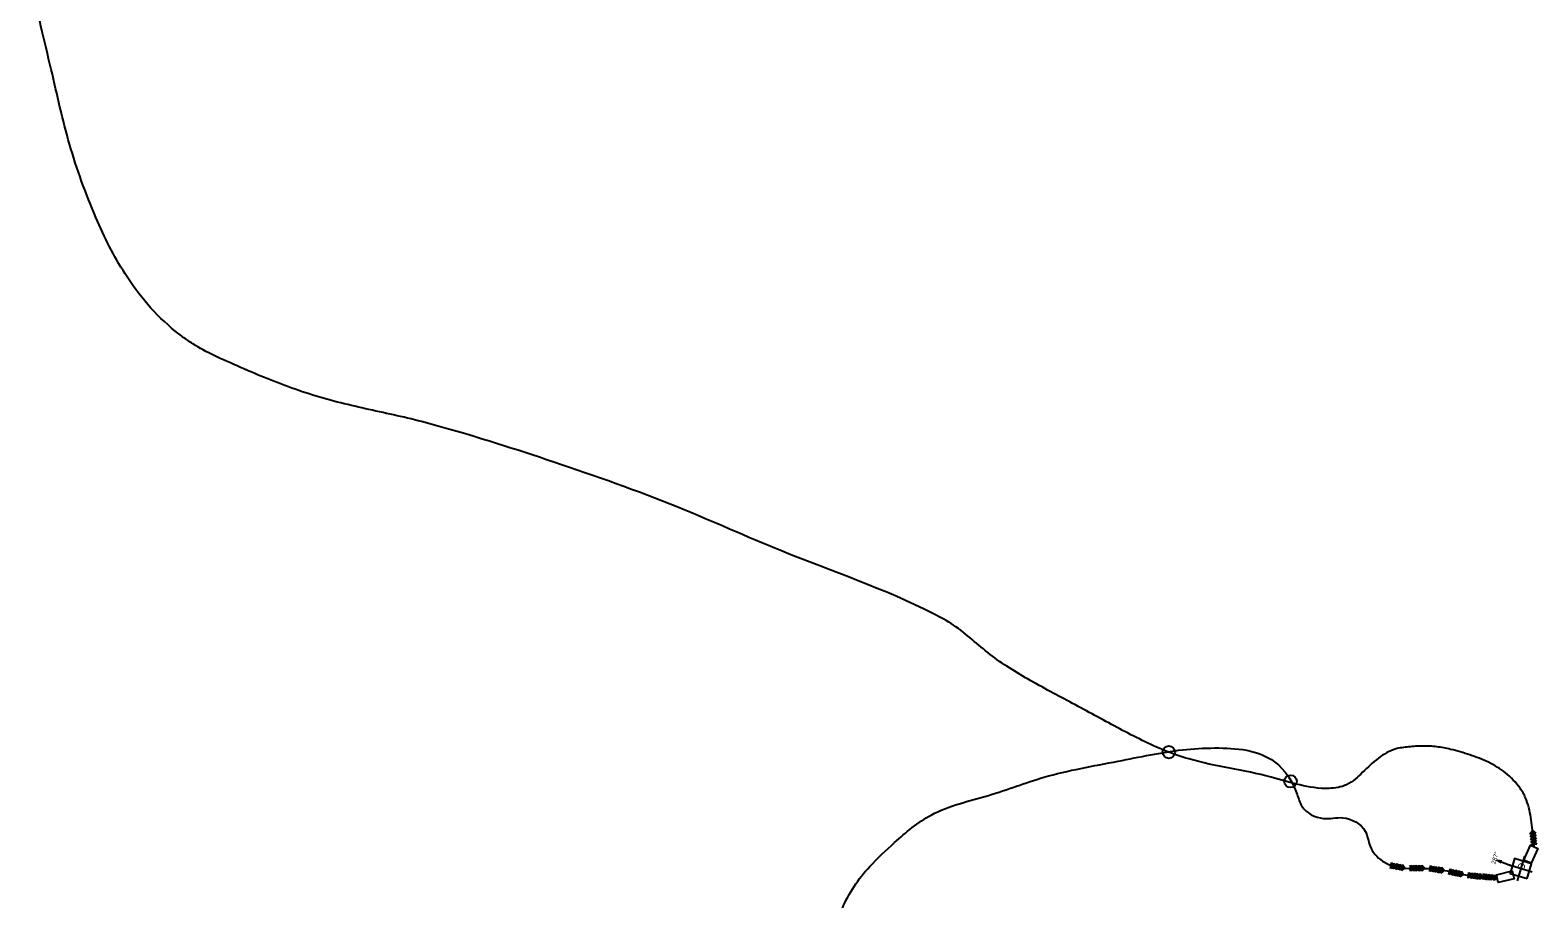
# Model space of a CAD drawing. Extents: x 387828 to 391861, y 7650362 to 7652502.
# Drawn here: x 387882.1 to 388052.5, y 7652108.1 to 7652206.3 of the extents above; entities that cross this region are included whole.
import ezdxf

# ---------------------------------------------------------------- set-up
doc = ezdxf.new("R2010")
doc.units = 0
for name, color, linetype in [('Blocos de area de avaliacao', 7, 'Continuous'), ('Blocos de producao br', 7, 'Continuous'), ('Cruzamento', 7, 'Continuous'), ('Dutos flexiveis', 7, 'Continuous'), ('Sinalizacao', 7, 'Continuous'), ('Texto dos gasodutos', 7, 'Continuous')]:
    doc.layers.add(name, color=color, linetype=linetype)

msp = doc.modelspace()

# ---------------------------------------------------------------- linework, layer by layer
at = {"layer": 'Blocos de area de avaliacao'}
for p, q in [((388047.9603292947, 7652112.509162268), (388049.6660734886, 7652111.858066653)), ((388051.901559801, 7652111.174610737), (388049.34319681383, 7652111.956779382)), ((388051.04635578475, 7652112.952465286), (388050.1984008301, 7652110.1789248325))]:
    msp.add_line(p, q, dxfattribs=at)
msp.add_lwpolyline([(388048.38287911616, 7652112.214074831), (388047.9603292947, 7652112.509162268), (388048.4720322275, 7652112.447638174)], dxfattribs=at)
at = {"layer": 'Blocos de producao br'}
for points in [[(388050.96772789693, 7652112.53604999), (388051.70532456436, 7652114.2162810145), (388052.54315073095, 7652113.848487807), (388051.8055540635, 7652112.168256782)], [(388047.8539045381, 7652110.870332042), (388049.6345597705, 7652111.313606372), (388049.85559312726, 7652110.425704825), (388048.0749378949, 7652109.982430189)]]:
    msp.add_lwpolyline(points, close=True, dxfattribs=at)
at = {"layer": 'Cruzamento'}
for centre in [(388010.8431242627, 7652124.717128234), (388024.58300245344, 7652121.434327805)]:
    msp.add_circle(centre, 0.7050177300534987, dxfattribs=at)
at = {"layer": 'Dutos flexiveis'}
for points in [[(388052.1426093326, 7652114.027375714), (388051.91000000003, 7652116.22), (388051.516732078, 7652118.479517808), (388051.14450636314, 7652119.574611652), (388050.87385052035, 7652120.114166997), (388050.5313486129, 7652120.648651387), (388048.8822293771, 7652122.386417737), (388046.96220465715, 7652123.585584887), (388044.864725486, 7652124.414286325), (388042.6832428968, 7652125.040655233), (388041.12194433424, 7652125.332635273), (388039.5223364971, 7652125.41788934), (388037.9409747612, 7652125.321987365), (388036.4344148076, 7652125.070498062), (388034.5261635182, 7652124.059678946), (388032.74273232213, 7652122.451738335), (388030.93271248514, 7652121.0424277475), (388028.944694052, 7652120.627499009), (388022.38694814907, 7652121.9071770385), (388013.09184148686, 7652123.964030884), (388010.41227454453, 7652124.8882036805), (388007.83105075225, 7652126.058778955), (388002.7895391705, 7652128.704348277), (387997.75690481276, 7652131.4113791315), (387992.81115970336, 7652134.249455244), (387990.64983336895, 7652135.767823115), (387988.5990002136, 7652137.464796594), (387986.50889736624, 7652139.085880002), (387984.22976226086, 7652140.376578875), (387967.04578478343, 7652147.475676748), (387955.33999511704, 7652152.4103787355), (387941.3134736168, 7652157.51206), (387928.35414746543, 7652161.552506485), (387925.2033695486, 7652162.382226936), (387922.02416302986, 7652163.103111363), (387918.84024231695, 7652163.814135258), (387915.67532242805, 7652164.614274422), (387909.3855311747, 7652166.7620087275), (387906.3099526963, 7652168.043193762), (387903.25013183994, 7652169.41), (387900.8121295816, 7652170.705623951), (387899.6609988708, 7652171.468749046), (387898.5465346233, 7652172.320802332), (387895.4376369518, 7652175.326235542), (387892.8787127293, 7652178.785263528), (387891.08650654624, 7652181.900448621), (387889.5796160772, 7652185.140767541), (387886.60210852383, 7652193.429089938), (387884.526090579, 7652201.868390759), (387882.3878279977, 7652211.720953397), (387882.16443922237, 7652213.858641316), (387882.2749983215, 7652216.02211005), (387882.64460036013, 7652218.190555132), (387883.19834009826, 7652220.343171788), (387883.7089428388, 7652221.81122959), (387884.35989165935, 7652223.188933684), (387885.15630787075, 7652224.503875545), (387886.1033140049, 7652225.783645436), (387888.4420777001, 7652228.289718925), (387889.75898922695, 7652229.307202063), (387891.23627582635, 7652230.137569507)], [(387996.45363353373, 7652022.634781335), (387997.33028870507, 7652033.655266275), (387998.62453199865, 7652040.779034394), (387999.221482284, 7652052.214446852), (387998.95, 7652059.012377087), (387996.62920346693, 7652065.404699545), (387993.1018854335, 7652070.481238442), (387987.7425565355, 7652076.419392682), (387984.70993285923, 7652078.996700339), (387980.73083468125, 7652082.5448841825), (387976.4977788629, 7652087.091991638), (387973.98176000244, 7652091.08594409), (387972.8787707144, 7652095.216200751), (387972.3570958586, 7652099.801324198), (387972.93239875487, 7652103.213922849), (387973.9494534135, 7652107.049292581), (387977.04101046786, 7652111.801097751), (387979.8398440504, 7652114.505278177), (387983.9645554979, 7652117.621005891), (387990.47256385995, 7652119.843109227), (387996.71472670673, 7652121.891180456), (388005.1127326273, 7652123.709367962), (388012.39015533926, 7652124.987872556), (388016.0371050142, 7652125.196237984), (388022.7907739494, 7652123.639071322), (388025.33534470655, 7652119.957836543), (388025.8908832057, 7652118.594798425), (388028.2920700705, 7652117.2328595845), (388030.48815729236, 7652117.309378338), (388033.0258842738, 7652115.7946321), (388033.5891103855, 7652114.094854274), (388034.9798687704, 7652112.42145024), (388037.03532578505, 7652111.665571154), (388040.7521915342, 7652111.537215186), (388044.8975392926, 7652110.747914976), (388047.94784936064, 7652110.49295053)]]:
    msp.add_spline(points, degree=3, dxfattribs=at)
at = {"layer": 'Sinalizacao'}
for p, q in [((388051.64188940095, 7652115.50404767), (388051.9378597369, 7652115.857313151)), ((388052.30385540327, 7652115.5772380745), (388051.64188940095, 7652115.50404767)), ((388051.64188940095, 7652115.50404767), (388051.97287240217, 7652115.54064272)), ((388051.64188940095, 7652115.50404767), (388051.97287240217, 7652115.54064272)), ((388051.6769020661, 7652115.18737724), (388051.97287240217, 7652115.54064272)), ((388052.33886837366, 7652115.26056795), (388051.6769020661, 7652115.18737724)), ((388051.6769020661, 7652115.18737724), (388052.0078850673, 7652115.223972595)), ((388051.6769020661, 7652115.18737724), (388052.0078850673, 7652115.223972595)), ((388051.71191503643, 7652114.870707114), (388052.0078850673, 7652115.223972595)), ((388052.37388103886, 7652114.943897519), (388051.71191503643, 7652114.870707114)), ((388051.9378597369, 7652115.857313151), (388052.30385540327, 7652115.5772380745)), ((388051.97287240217, 7652115.54064272), (388052.33886837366, 7652115.26056795)), ((388052.0078850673, 7652115.223972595), (388052.37388103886, 7652114.943897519)), ((388051.71191503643, 7652114.870707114), (388052.04289803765, 7652114.907302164)), ((388051.71191503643, 7652114.870707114), (388052.04289803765, 7652114.907302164)), ((388051.7469277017, 7652114.554036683), (388052.04289803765, 7652114.907302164)), ((388052.40889370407, 7652114.627227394), (388051.7469277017, 7652114.554036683)), ((388051.7469277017, 7652114.554036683), (388052.07791070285, 7652114.590632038)), ((388051.7469277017, 7652114.554036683), (388052.07791070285, 7652114.590632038)), ((388051.781940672, 7652114.237366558), (388052.07791070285, 7652114.590632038)), ((388052.4439066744, 7652114.310556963), (388051.781940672, 7652114.237366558)), ((388051.781940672, 7652114.237366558), (388052.11292367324, 7652114.273961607)), ((388051.781940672, 7652114.237366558), (388052.11292367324, 7652114.273961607)), ((388052.04289803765, 7652114.907302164), (388052.40889370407, 7652114.627227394)), ((388052.07791070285, 7652114.590632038), (388052.4439066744, 7652114.310556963)), ((388035.88974608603, 7652111.58747795), (388036.00492263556, 7652112.243443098)), ((388036.26113406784, 7652111.86036256), (388035.88974608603, 7652111.58747795)), ((388036.00492263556, 7652112.243443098), (388035.94733451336, 7652111.915460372)), ((388036.00492263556, 7652112.243443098), (388035.94733451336, 7652111.915460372)), ((388036.00492263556, 7652112.243443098), (388036.26113406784, 7652111.86036256)), ((388036.2035456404, 7652111.532379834), (388036.31872219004, 7652112.1883449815)), ((388036.57493362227, 7652111.805264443), (388036.2035456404, 7652111.532379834)), ((388036.31872219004, 7652112.1883449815), (388036.26113406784, 7652111.86036256)), ((388036.31872219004, 7652112.1883449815), (388036.26113406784, 7652111.86036256)), ((388036.31872219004, 7652112.1883449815), (388036.57493362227, 7652111.805264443)), ((388036.5173451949, 7652111.477281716), (388036.63252174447, 7652112.13324717)), ((388036.8887331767, 7652111.750166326), (388036.5173451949, 7652111.477281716)), ((388036.63252174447, 7652112.13324717), (388036.57493362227, 7652111.805264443)), ((388036.63252174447, 7652112.13324717), (388036.57493362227, 7652111.805264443)), ((388036.63252174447, 7652112.13324717), (388036.8887331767, 7652111.750166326)), ((388036.8311447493, 7652111.422183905), (388036.946321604, 7652112.078149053)), ((388037.20253273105, 7652111.695068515), (388036.8311447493, 7652111.422183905)), ((388036.946321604, 7652112.078149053), (388036.8887331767, 7652111.750166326)), ((388036.946321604, 7652112.078149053), (388036.8887331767, 7652111.750166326)), ((388036.946321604, 7652112.078149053), (388037.20253273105, 7652111.695068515)), ((388037.1449443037, 7652111.3670857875), (388037.2601211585, 7652112.023050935)), ((388037.51633228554, 7652111.639970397), (388037.1449443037, 7652111.3670857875)), ((388037.2601211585, 7652112.023050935), (388037.20253273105, 7652111.695068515)), ((388037.2601211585, 7652112.023050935), (388037.20253273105, 7652111.695068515)), ((388037.2601211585, 7652112.023050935), (388037.51633228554, 7652111.639970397)), ((388038.16457167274, 7652111.280686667), (388038.16457167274, 7652111.946686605)), ((388038.16457167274, 7652111.946686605), (388038.16457167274, 7652111.613686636)), ((388038.16457167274, 7652111.946686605), (388038.16457167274, 7652111.613686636)), ((388038.16457167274, 7652111.946686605), (388038.4831714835, 7652111.613686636)), ((388038.4831714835, 7652111.613686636), (388038.16457167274, 7652111.280686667)), ((388038.4831714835, 7652111.280686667), (388038.4831714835, 7652111.946686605)), ((388038.4831714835, 7652111.946686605), (388038.4831714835, 7652111.613686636)), ((388038.4831714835, 7652111.946686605), (388038.4831714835, 7652111.613686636)), ((388038.4831714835, 7652111.946686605), (388038.8017715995, 7652111.613686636)), ((388038.8017715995, 7652111.613686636), (388038.4831714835, 7652111.280686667)), ((388038.8017715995, 7652111.280686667), (388038.8017715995, 7652111.946686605)), ((388038.8017715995, 7652111.946686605), (388038.8017715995, 7652111.613686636)), ((388038.8017715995, 7652111.946686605), (388038.8017715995, 7652111.613686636)), ((388038.8017715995, 7652111.946686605), (388039.12037171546, 7652111.613686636)), ((388039.12037171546, 7652111.613686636), (388038.8017715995, 7652111.280686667)), ((388039.12037171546, 7652111.280686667), (388039.12037171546, 7652111.946686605)), ((388039.12037171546, 7652111.946686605), (388039.12037171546, 7652111.613686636)), ((388039.12037171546, 7652111.946686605), (388039.12037171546, 7652111.613686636)), ((388039.12037171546, 7652111.946686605), (388039.4389715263, 7652111.613686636)), ((388039.4389715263, 7652111.613686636), (388039.12037171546, 7652111.280686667)), ((388039.4389715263, 7652111.280686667), (388039.4389715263, 7652111.946686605)), ((388039.4389715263, 7652111.946686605), (388039.4389715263, 7652111.613686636)), ((388039.4389715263, 7652111.946686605), (388039.4389715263, 7652111.613686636)), ((388039.4389715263, 7652111.946686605), (388039.75757164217, 7652111.613686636)), ((388039.75757164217, 7652111.613686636), (388039.4389715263, 7652111.280686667)), ((388040.32635364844, 7652111.247911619), (388040.4277895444, 7652111.906141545)), ((388040.6919547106, 7652111.528501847), (388040.32635364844, 7652111.247911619)), ((388040.4277895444, 7652111.906141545), (388040.37707174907, 7652111.577026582)), ((388040.4277895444, 7652111.906141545), (388040.37707174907, 7652111.577026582)), ((388040.4277895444, 7652111.906141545), (388040.6919547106, 7652111.528501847)), ((388040.64123661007, 7652111.199386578), (388040.7426725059, 7652111.85761681)), ((388040.7426725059, 7652111.85761681), (388040.6919547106, 7652111.528501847)), ((388040.7426725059, 7652111.85761681), (388040.6919547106, 7652111.528501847)), ((388040.7426725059, 7652111.85761681), (388041.0068376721, 7652111.47997711)), ((388040.9561195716, 7652111.150861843), (388041.0575554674, 7652111.809092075)), ((388041.0575554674, 7652111.809092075), (388041.0068376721, 7652111.47997711)), ((388041.0575554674, 7652111.809092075), (388041.0068376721, 7652111.47997711)), ((388041.0575554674, 7652111.809092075), (388041.3217206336, 7652111.43145207)), ((388041.2710025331, 7652111.102337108), (388041.3724387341, 7652111.76056734)), ((388041.3724387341, 7652111.76056734), (388041.3217206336, 7652111.43145207)), ((388041.3724387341, 7652111.76056734), (388041.3217206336, 7652111.43145207)), ((388041.3724387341, 7652111.76056734), (388041.6366035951, 7652111.382927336)), ((388041.5858857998, 7652111.0538123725), (388041.6873216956, 7652111.712042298)), ((388041.6873216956, 7652111.712042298), (388041.6366035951, 7652111.382927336)), ((388041.6873216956, 7652111.712042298), (388041.6366035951, 7652111.382927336)), ((388041.6873216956, 7652111.712042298), (388041.9514865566, 7652111.3344026)), ((388042.49188268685, 7652110.882083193), (388042.62026978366, 7652111.535591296)), ((388042.62026978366, 7652111.535591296), (388042.55607623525, 7652111.208837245)), ((388042.62026978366, 7652111.535591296), (388042.55607623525, 7652111.208837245)), ((388042.62026978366, 7652111.535591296), (388042.8687002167, 7652111.14741966)), ((388041.0068376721, 7652111.47997711), (388040.64123661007, 7652111.199386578)), ((388041.3217206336, 7652111.43145207), (388040.9561195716, 7652111.150861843)), ((388041.6366035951, 7652111.382927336), (388041.2710025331, 7652111.102337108)), ((388041.9514865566, 7652111.3344026), (388041.5858857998, 7652111.0538123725)), ((388042.8687002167, 7652111.14741966), (388042.49188268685, 7652110.882083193)), ((388042.8045066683, 7652110.820665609), (388042.93289376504, 7652111.474173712)), ((388043.1813245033, 7652111.086002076), (388042.8045066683, 7652110.820665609)), ((388042.93289376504, 7652111.474173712), (388042.8687002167, 7652111.14741966)), ((388042.93289376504, 7652111.474173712), (388042.8687002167, 7652111.14741966)), ((388042.93289376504, 7652111.474173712), (388043.1813245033, 7652111.086002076)), ((388043.1171309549, 7652110.759248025), (388043.24551805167, 7652111.412755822)), ((388043.4939484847, 7652111.024584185), (388043.1171309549, 7652110.759248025)), ((388043.24551805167, 7652111.412755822), (388043.1813245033, 7652111.086002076)), ((388043.24551805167, 7652111.412755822), (388043.1813245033, 7652111.086002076)), ((388043.24551805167, 7652111.412755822), (388043.4939484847, 7652111.024584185)), ((388043.4297549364, 7652110.697830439), (388043.5581420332, 7652111.351338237)), ((388043.8065724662, 7652110.963166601), (388043.4297549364, 7652110.697830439)), ((388043.5581420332, 7652111.351338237), (388043.4939484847, 7652111.024584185)), ((388043.5581420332, 7652111.351338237), (388043.4939484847, 7652111.024584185)), ((388043.5581420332, 7652111.351338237), (388043.8065724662, 7652110.963166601)), ((388043.7423789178, 7652110.636412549), (388043.8707663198, 7652111.289920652)), ((388044.11919675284, 7652110.901749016), (388043.7423789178, 7652110.636412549)), ((388043.8707663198, 7652111.289920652), (388043.8065724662, 7652110.963166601)), ((388043.8707663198, 7652111.289920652), (388043.8065724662, 7652110.963166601)), ((388043.8707663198, 7652111.289920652), (388044.11919675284, 7652110.901749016)), ((388044.6720566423, 7652110.471092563), (388044.7384511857, 7652111.133774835)), ((388045.02226691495, 7652110.770672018), (388044.6720566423, 7652110.471092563)), ((388044.7384511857, 7652111.133774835), (388044.7052540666, 7652110.802433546)), ((388044.7384511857, 7652111.133774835), (388044.7052540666, 7652110.802433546)), ((388044.7384511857, 7652111.133774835), (388045.02226691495, 7652110.770672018)), ((388044.98906949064, 7652110.43933073), (388045.0554640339, 7652111.102013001)), ((388045.33927976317, 7652110.738910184), (388044.98906949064, 7652110.43933073)), ((388045.0554640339, 7652111.102013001), (388045.02226691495, 7652110.770672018)), ((388045.0554640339, 7652111.102013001), (388045.02226691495, 7652110.770672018)), ((388045.0554640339, 7652111.102013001), (388045.33927976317, 7652110.738910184)), ((388045.3060823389, 7652110.407569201), (388045.37247688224, 7652111.070251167)), ((388045.65629261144, 7652110.707148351), (388045.3060823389, 7652110.407569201)), ((388045.37247688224, 7652111.070251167), (388045.33927976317, 7652110.738910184)), ((388045.37247688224, 7652111.070251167), (388045.33927976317, 7652110.738910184)), ((388045.37247688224, 7652111.070251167), (388045.65629261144, 7652110.707148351)), ((388045.62309518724, 7652110.375807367), (388045.6894897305, 7652111.038489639)), ((388045.9733054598, 7652110.675386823), (388045.62309518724, 7652110.375807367)), ((388045.6894897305, 7652111.038489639), (388045.65629261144, 7652110.707148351)), ((388045.6894897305, 7652111.038489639), (388045.65629261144, 7652110.707148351)), ((388045.6894897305, 7652111.038489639), (388045.9733054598, 7652110.675386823)), ((388045.9401080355, 7652110.344045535), (388046.0065025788, 7652111.006727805)), ((388046.29031830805, 7652110.643624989), (388045.9401080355, 7652110.344045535)), ((388046.0065025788, 7652111.006727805), (388045.9733054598, 7652110.675386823)), ((388046.0065025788, 7652111.006727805), (388045.9733054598, 7652110.675386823)), ((388046.0065025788, 7652111.006727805), (388046.29031830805, 7652110.643624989)), ((388046.32361400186, 7652110.336642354), (388046.39000854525, 7652110.999324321)), ((388046.6738242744, 7652110.636221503), (388046.32361400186, 7652110.336642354)), ((388046.39000854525, 7652110.999324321), (388046.3568114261, 7652110.667983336)), ((388046.39000854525, 7652110.999324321), (388046.3568114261, 7652110.667983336)), ((388046.39000854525, 7652110.999324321), (388046.6738242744, 7652110.636221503)), ((388046.6406268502, 7652110.30488052), (388046.70702139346, 7652110.967562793)), ((388046.9908371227, 7652110.604459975), (388046.6406268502, 7652110.30488052)), ((388046.70702139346, 7652110.967562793), (388046.6738242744, 7652110.636221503)), ((388046.70702139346, 7652110.967562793), (388046.6738242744, 7652110.636221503)), ((388046.70702139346, 7652110.967562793), (388046.9908371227, 7652110.604459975)), ((388046.95763969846, 7652110.273118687), (388047.02403424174, 7652110.935800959)), ((388047.307849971, 7652110.572698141), (388046.95763969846, 7652110.273118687)), ((388047.02403424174, 7652110.935800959), (388046.9908371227, 7652110.604459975)), ((388047.02403424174, 7652110.935800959), (388046.9908371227, 7652110.604459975)), ((388047.02403424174, 7652110.935800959), (388047.307849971, 7652110.572698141)), ((388047.2746525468, 7652110.241356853), (388047.34104709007, 7652110.904039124)), ((388047.6248628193, 7652110.540936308), (388047.2746525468, 7652110.241356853)), ((388047.34104709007, 7652110.904039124), (388047.307849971, 7652110.572698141)), ((388047.34104709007, 7652110.904039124), (388047.307849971, 7652110.572698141)), ((388047.34104709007, 7652110.904039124), (388047.6248628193, 7652110.540936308)), ((388047.59166539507, 7652110.209595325), (388047.65805993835, 7652110.872277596)), ((388047.9418756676, 7652110.50917478), (388047.59166539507, 7652110.209595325)), ((388047.65805993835, 7652110.872277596), (388047.6248628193, 7652110.540936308)), ((388047.65805993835, 7652110.872277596), (388047.6248628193, 7652110.540936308)), ((388047.65805993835, 7652110.872277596), (388047.9418756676, 7652110.50917478))]:
    msp.add_line(p, q, dxfattribs=at)
at = {"layer": 'Texto dos gasodutos'}
msp.add_lwpolyline([(388051.32285775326, 7652110.436556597), (388051.83450819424, 7652112.110090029), (388049.9218988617, 7652112.694833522), (388049.41024811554, 7652111.021300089)], close=True, dxfattribs=at)

# ---------------------------------------------------------------- texts
at = {"layer": 'Blocos de area de avaliacao'}
msp.add_text('287°', height=0.49998000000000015, rotation=72.99999997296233, dxfattribs=at).set_placement((388047.74, 7652112.0200000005))
at = {"layer": 'Texto dos gasodutos'}
msp.add_text('O', height=0.7620000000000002, rotation=72.99999997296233, dxfattribs=at).set_placement((388050.94, 7652111.3100000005))

doc.saveas('drawing.dxf')
